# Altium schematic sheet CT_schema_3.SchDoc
size 282 x 147 mm
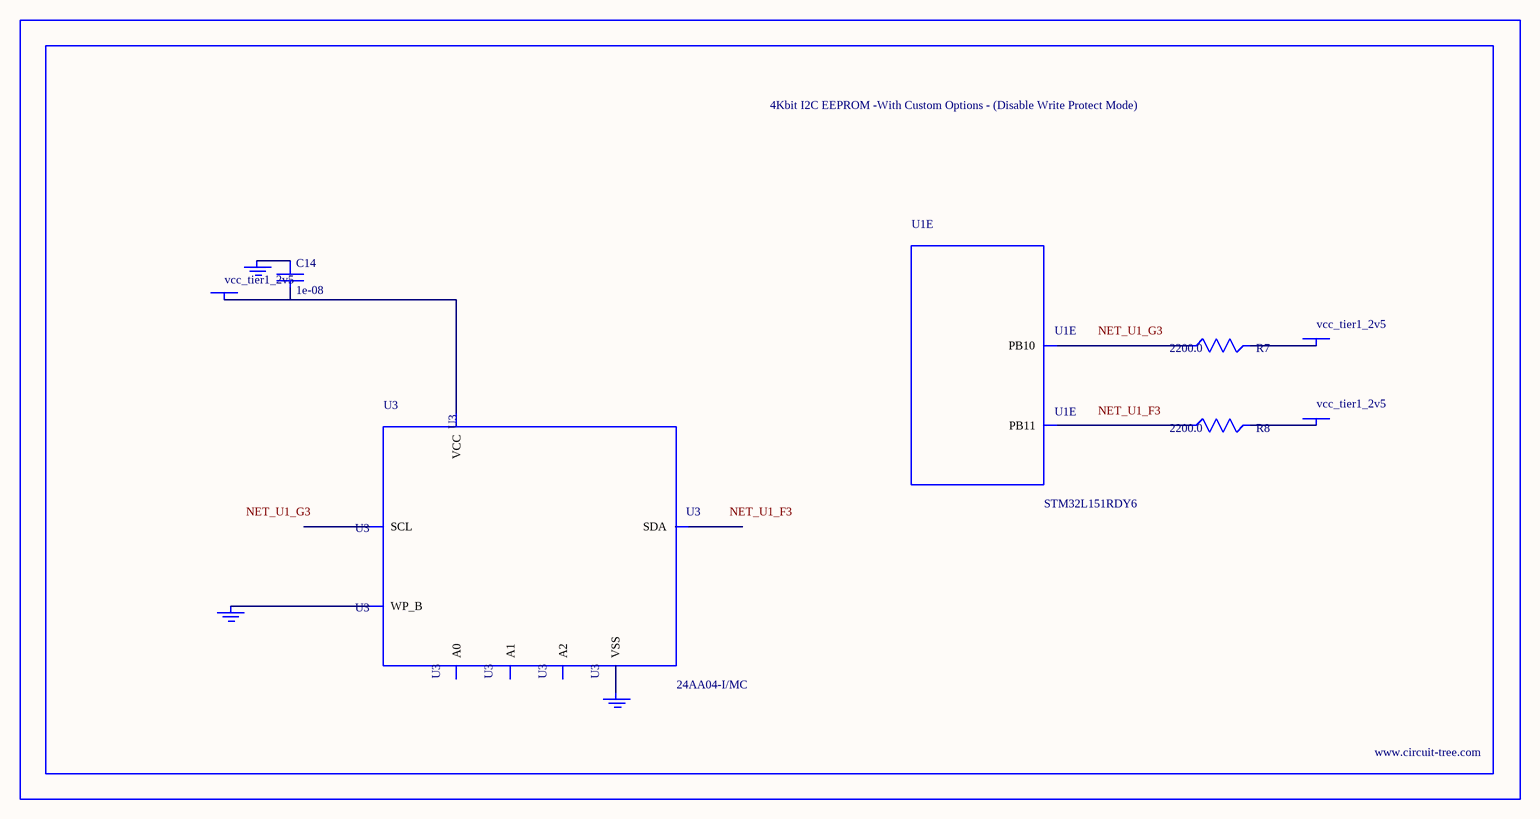
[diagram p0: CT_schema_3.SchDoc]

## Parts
BORDER2  (no value)
C14  1e-08  [C0402]
GND_INSTANCE_2_0  (no value)
GND_INSTANCE_2_1  (no value)
GND_INSTANCE_2_2  (no value)
POWER_INSTANCE_2_0  vcc_tier1_2v5
POWER_INSTANCE_2_1  vcc_tier1_2v5
POWER_INSTANCE_2_2  vcc_tier1_2v5
R7  2200.0  [R0603]
R8  2200.0  [R0603]
U1  STM32L151RDY6  [WLCSP64]  (part E of 8)
U3  24AA04-I/MC  [TDFN-8/6MM]

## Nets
NetC14_1: C14.1 GND_INSTANCE_2_1.0(GND)
NetC14_2: C14.2 POWER_INSTANCE_2_0.0(PWR) U3.8(VCC)
NetGND_INSTANCE_2_0_0: GND_INSTANCE_2_0.0(GND) U3.7(WP_B)
NetGND_INSTANCE_2_2_0: GND_INSTANCE_2_2.0(GND) U3.4(VSS)
NetPOWER_INSTANCE_2_1_0: POWER_INSTANCE_2_1.0(PWR) R7.2
NetPOWER_INSTANCE_2_2_0: POWER_INSTANCE_2_2.0(PWR) R8.2
NetR7_1: R7.1 U1.G3(PB10)
NetR8_1: R8.1 U1.F3(PB11)

Not connected (* = marked no-connect by the designer): U3 1(A0) 2(A1) 3(A2) 5(SDA) 6(SCL)

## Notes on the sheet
- Labels drawn without touching a wire or pin: NET_U1_F3, NET_U1_G3

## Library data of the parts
BORDER2 = BORDER_PAGE2
C14 = C0402C103K3RAC
GND_INSTANCE_2_0-GND_INSTANCE_2_2 = GND
POWER_INSTANCE_2_0-POWER_INSTANCE_2_2 = PWR
R7 R8 = RC0603JR-072K2L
